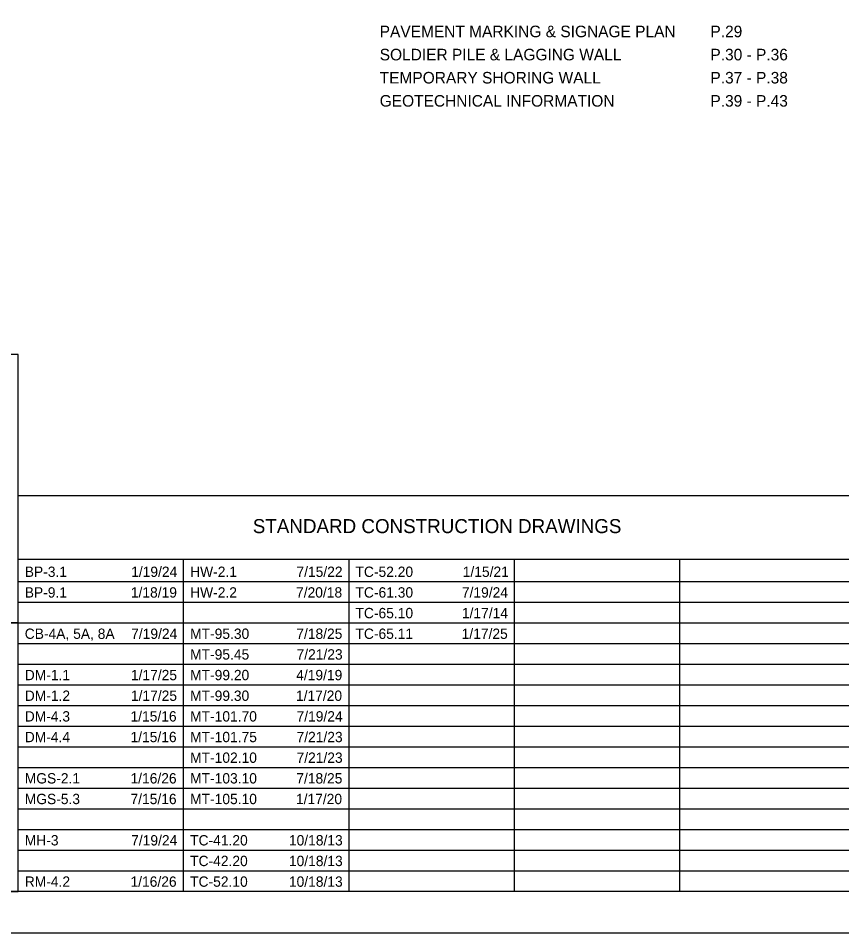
# Model space of a CAD drawing. Extents: x 0 to 34, y 0 to 22.
# Drawn here: x 10.15 to 20.11, y 0 to 11.07 of the extents above; entities that cross this region are included whole.
import ezdxf

# ---------------------------------------------------------------- set-up
doc = ezdxf.new("R2010")
doc.units = 0
for name, color, linetype in [('SH_Border', 7, 'Continuous'), ('SH_Cut_Line', 7, 'Continuous'), ('SH_Data', 7, 'Continuous'), ('SH_Text', 7, 'Continuous')]:
    doc.layers.add(name, color=color, linetype=linetype)

msp = doc.modelspace()

# ---------------------------------------------------------------- linework, layer by layer
at = {"layer": 'SH_Border'}
msp.add_lwpolyline([(1.5, 21.5), (33.5, 21.5), (33.5, 0.5), (1.5, 0.5)], close=True, dxfattribs=at)
at = {"layer": 'SH_Cut_Line'}
msp.add_lwpolyline([(0, 0), (34, 0), (34, 22), (0, 22)], close=True, dxfattribs=at)
at = {"layer": 'SH_Data'}
for p, q in [((10.15, 5.292), (23.6, 5.292)), ((10.15, 0.5), (10.15, 5.292)), ((10.15, 4.521), (23.6, 4.521)), ((12.15, 0.5), (12.15, 4.521)), ((14.15, 0.5), (14.15, 4.521)), ((16.15, 0.5), (16.15, 4.521)), ((18.15, 0.5), (18.15, 4.521)), ((10.15, 4.25), (23.6, 4.25)), ((10.15, 4), (23.6, 4)), ((10.15, 3.75), (23.6, 3.75)), ((10.15, 3.5), (23.6, 3.5)), ((10.15, 3.25), (23.6, 3.25)), ((10.15, 3), (23.6, 3)), ((10.15, 2.75), (23.6, 2.75)), ((10.15, 2.5), (23.6, 2.5)), ((10.15, 2.25), (23.6, 2.25)), ((10.15, 2), (23.6, 2)), ((10.15, 1.75), (23.6, 1.75)), ((10.15, 1.5), (23.6, 1.5)), ((10.15, 1.25), (23.6, 1.25)), ((10.15, 1), (23.6, 1)), ((10.15, 0.75), (23.6, 0.75))]:
    msp.add_line(p, q, dxfattribs=at)
for points in [[(10.15, 7), (7.35, 7), (7.35, 3.75), (10.15, 3.75)], [(10.15, 3.75), (7.35, 3.75), (7.35, 0.5), (10.15, 0.5)]]:
    msp.add_lwpolyline(points, close=True, dxfattribs=at)

# ---------------------------------------------------------------- texts
at = {"layer": 'SH_Text'}
for s, height, p in [('PAVEMENT MARKING & SIGNAGE PLAN', 0.14, (14.521, 10.838)), ('P.29', 0.14, (18.521, 10.838)), ('SOLDIER PILE & LAGGING WALL', 0.14, (14.521, 10.558)), ('P.30 - P.36', 0.14, (18.521, 10.558)), ('TEMPORARY SHORING WALL', 0.14, (14.521, 10.278)), ('P.37 - P.38', 0.14, (18.521, 10.278)), ('GEOTECHNICAL INFORMATION', 0.14, (14.521, 9.998)), ('P.39 - P.43', 0.14, (18.521, 9.998)), ('STANDARD CONSTRUCTION DRAWINGS', 0.17, (12.986, 4.836)), ('BP-3.1', 0.125, (10.228, 4.306)), ('1/19/24', 0.125, (11.515, 4.306)), ('HW-2.1', 0.125, (12.228, 4.306)), ('7/15/22', 0.125, (13.514, 4.306)), ('TC-52.20', 0.125, (14.228, 4.306)), ('1/15/21', 0.125, (15.525, 4.306)), ('BP-9.1', 0.125, (10.228, 4.056)), ('1/18/19', 0.125, (11.511, 4.056)), ('HW-2.2', 0.125, (12.228, 4.056)), ('7/20/18', 0.125, (13.509, 4.056)), ('TC-61.30', 0.125, (14.228, 4.056)), ('7/19/24', 0.125, (15.515, 4.056)), ('TC-65.10', 0.125, (14.228, 3.806)), ('1/17/14', 0.125, (15.515, 3.806)), ('CB-4A, 5A, 8A', 0.125, (10.228, 3.556)), ('7/19/24', 0.125, (11.515, 3.556)), ('MT-95.30', 0.125, (12.228, 3.556)), ('7/18/25', 0.125, (13.512, 3.556)), ('TC-65.11', 0.125, (14.228, 3.556)), ('1/17/25', 0.125, (15.512, 3.556)), ('MT-95.45', 0.125, (12.228, 3.306)), ('7/21/23', 0.125, (13.515, 3.306)), ('DM-1.1', 0.125, (10.228, 3.056)), ('1/17/25', 0.125, (11.512, 3.056)), ('MT-99.20', 0.125, (12.228, 3.056)), ('4/19/19', 0.125, (13.511, 3.056)), ('DM-1.2', 0.125, (10.228, 2.806)), ('1/17/25', 0.125, (11.512, 2.806)), ('MT-99.30', 0.125, (12.228, 2.806)), ('1/17/20', 0.125, (13.508, 2.806)), ('DM-4.3', 0.125, (10.228, 2.556)), ('1/15/16', 0.125, (11.507, 2.556)), ('MT-101.70', 0.125, (12.228, 2.556)), ('7/19/24', 0.125, (13.515, 2.556)), ('1/15/16', 0.125, (11.507, 2.306)), ('7/21/23', 0.125, (13.515, 2.306)), ('DM-4.4', 0.125, (10.228, 2.306)), ('MT-101.75', 0.125, (12.228, 2.306)), ('MT-102.10', 0.125, (12.228, 2.056)), ('7/21/23', 0.125, (13.515, 2.056)), ('MGS-2.1', 0.125, (10.228, 1.806)), ('1/16/26', 0.125, (11.507, 1.806)), ('MT-103.10', 0.125, (12.228, 1.806)), ('7/18/25', 0.125, (13.512, 1.806)), ('MGS-5.3', 0.125, (10.228, 1.556)), ('7/15/16', 0.125, (11.507, 1.556)), ('MT-105.10', 0.125, (12.228, 1.556)), ('1/17/20', 0.125, (13.508, 1.556)), ('MH-3', 0.125, (10.228, 1.056)), ('7/19/24', 0.125, (11.515, 1.056)), ('TC-41.20', 0.125, (12.228, 1.056)), ('10/18/13', 0.125, (13.423, 1.056)), ('TC-42.20', 0.125, (12.228, 0.806)), ('10/18/13', 0.125, (13.423, 0.806)), ('RM-4.2', 0.125, (10.228, 0.556)), ('1/16/26', 0.125, (11.507, 0.556)), ('TC-52.10', 0.125, (12.228, 0.556)), ('10/18/13', 0.125, (13.423, 0.556))]:
    msp.add_text(s, height=height, dxfattribs=at).set_placement(p)

doc.saveas('drawing.dxf')
